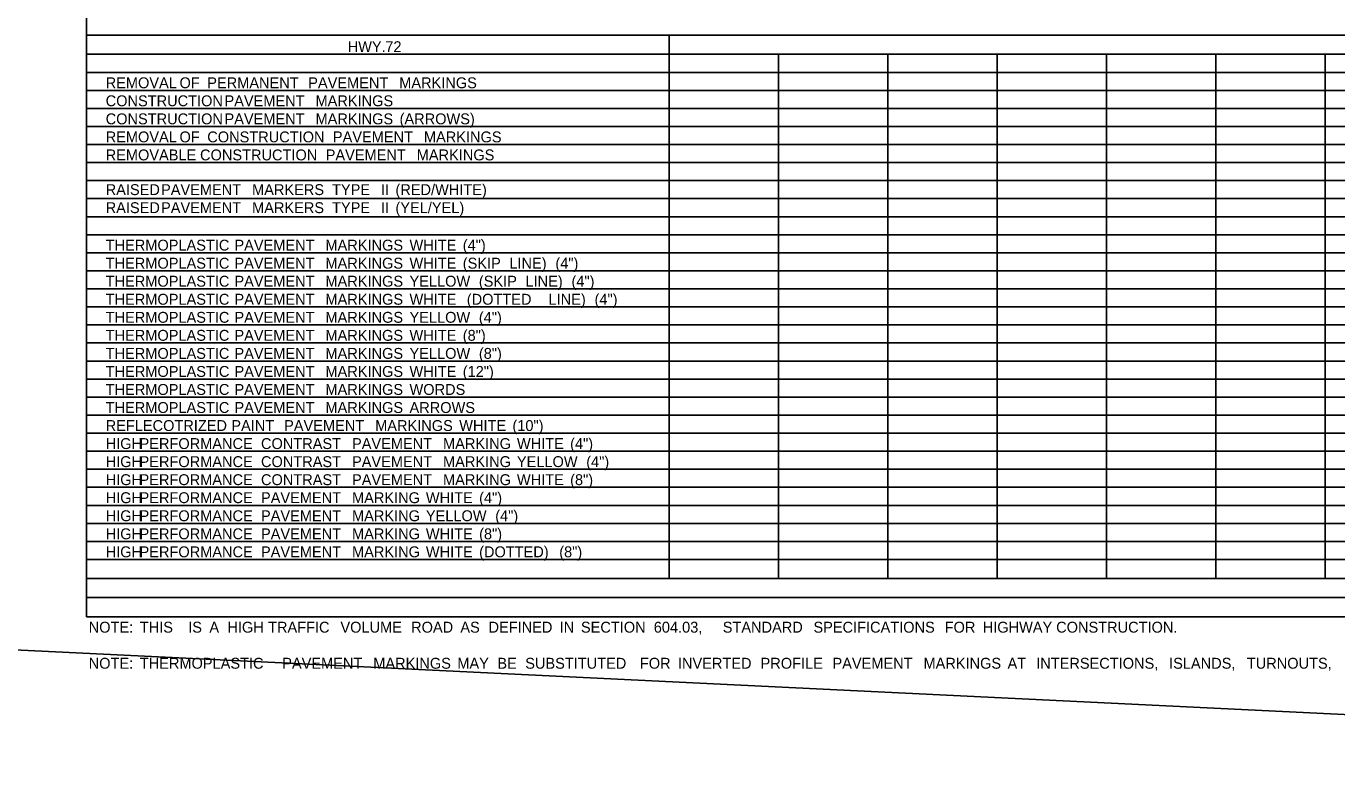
# Model space of a CAD drawing. Extents: x 1225909 to 1228704, y 151309 to 152305.
# Drawn here: x 1226559.5 to 1226949.3, y 151342 to 151561.1 of the extents above; entities that cross this region are included whole.
import ezdxf

# ---------------------------------------------------------------- set-up
doc = ezdxf.new("R2010")
doc.units = 0
doc.layers.add('R_Border', color=7, linetype='Continuous')
doc.layers.add('R_Dimension', color=7, linetype='Continuous')

msp = doc.modelspace()

# ---------------------------------------------------------------- linework, layer by layer
at = {"layer": 'R_Border'}
msp.add_lwpolyline([(1227672.06, 151397.84), (1227247.19, 151342), (1225968.58, 151404.15)], dxfattribs=at)
at = {"layer": 'R_Dimension'}
for p, q in [((1226577.42, 151385.44), (1226577.42, 151914.54)), ((1226577.42, 151558.44), (1228151.92, 151558.44)), ((1226750.73, 151396.81), (1226750.73, 151558.44)), ((1226577.42, 151552.76), (1228151.92, 151552.76)), ((1226783.25, 151396.81), (1226783.25, 151552.76)), ((1226815.77, 151396.81), (1226815.77, 151552.76)), ((1226848.28, 151396.81), (1226848.28, 151552.76)), ((1226880.8, 151396.81), (1226880.8, 151552.76)), ((1226913.31, 151396.81), (1226913.31, 151552.76)), ((1226945.83, 151396.81), (1226945.83, 151552.76)), ((1226577.42, 151547.39), (1228151.92, 151547.39)), ((1226577.42, 151542.02), (1228151.92, 151542.02)), ((1226577.42, 151536.66), (1228151.92, 151536.66)), ((1226577.42, 151531.29), (1228151.92, 151531.29)), ((1226577.42, 151525.92), (1228151.92, 151525.92)), ((1226577.42, 151520.56), (1228151.92, 151520.56)), ((1226577.42, 151515.19), (1228151.92, 151515.19)), ((1226577.42, 151509.82), (1228151.92, 151509.82)), ((1226577.42, 151504.46), (1228151.92, 151504.46)), ((1226577.42, 151499.09), (1228151.92, 151499.09)), ((1226577.42, 151493.72), (1228151.92, 151493.72)), ((1226577.42, 151488.36), (1228151.92, 151488.36)), ((1226577.42, 151482.99), (1228151.92, 151482.99)), ((1226577.42, 151477.62), (1228151.92, 151477.62)), ((1226577.42, 151472.26), (1228151.92, 151472.26)), ((1226577.42, 151466.89), (1228151.92, 151466.89)), ((1226577.42, 151461.52), (1228151.92, 151461.52)), ((1226577.42, 151456.16), (1228151.92, 151456.16)), ((1226577.42, 151450.79), (1228151.92, 151450.79)), ((1226577.42, 151445.42), (1228151.92, 151445.42)), ((1226577.42, 151440.06), (1228151.92, 151440.06)), ((1226577.42, 151434.69), (1228151.92, 151434.69)), ((1226577.42, 151429.32), (1228151.92, 151429.32)), ((1226577.42, 151423.96), (1228151.92, 151423.96)), ((1226577.42, 151418.59), (1228151.92, 151418.59)), ((1226577.42, 151413.22), (1228151.92, 151413.22)), ((1226577.42, 151407.86), (1228151.92, 151407.86)), ((1226577.42, 151402.49), (1228151.92, 151402.49)), ((1226577.42, 151396.81), (1228151.92, 151396.81)), ((1226577.42, 151391.13), (1228151.92, 151391.13)), ((1226577.42, 151385.44), (1228151.92, 151385.44))]:
    msp.add_line(p, q, dxfattribs=at)

# ---------------------------------------------------------------- texts
for s, height, p in [('HWY.', 3.238, (1226655.09, 151553.41)), (' 72', 3.238, (1226665.08, 151553.41)), ('REMOVAL', 3.238, (1226583.1, 151542.67)), (' OF', 3.238, (1226603.86, 151542.67)), (' PERMANENT', 3.238, (1226612.12, 151542.67)), (' PAVEMENT', 3.238, (1226642.15, 151542.67)), (' MARKINGS', 3.238, (1226669.22, 151542.67)), ('CONSTRUCTION', 3.2378, (1226583.1, 151537.31)), (' PAVEMENT', 3.238, (1226617.24, 151537.31)), (' MARKINGS', 3.238, (1226644.32, 151537.31)), ('CONSTRUCTION', 3.2378, (1226583.1, 151531.94)), (' PAVEMENT', 3.238, (1226617.24, 151531.94)), (' MARKINGS', 3.238, (1226644.32, 151531.94)), (' (ARROWS)', 3.238, (1226669.33, 151531.94)), ('REMOVAL', 3.238, (1226583.1, 151526.57)), (' OF', 3.238, (1226603.86, 151526.57)), (' CONSTRUCTION', 3.2378, (1226612.12, 151526.57)), (' PAVEMENT', 3.238, (1226649.49, 151526.57)), (' MARKINGS', 3.238, (1226676.57, 151526.57)), ('REMOVABLE', 3.238, (1226583.1, 151521.21)), (' CONSTRUCTION', 3.2378, (1226609.97, 151521.21)), (' PAVEMENT', 3.238, (1226647.35, 151521.21)), (' MARKINGS', 3.238, (1226674.43, 151521.21)), ('RAISED', 3.238, (1226583.1, 151510.89)), (' PAVEMENT', 3.238, (1226598.37, 151510.89)), (' MARKERS', 3.238, (1226625.45, 151510.89)), (' TYPE', 3.238, (1226649.24, 151510.89)), (' II', 3.238, (1226663.79, 151510.89)), (' (RED/WHITE)', 3.2378, (1226668.1, 151510.89)), ('RAISED', 3.238, (1226583.1, 151505.52)), (' PAVEMENT', 3.238, (1226598.37, 151505.52)), (' MARKERS', 3.238, (1226625.45, 151505.52)), (' TYPE', 3.238, (1226649.24, 151505.52)), (' II', 3.238, (1226663.79, 151505.52)), (' (YEL/YEL)', 3.238, (1226668.1, 151505.52)), ('THERMOPLASTIC', 3.2378, (1226583.1, 151494.37)), (' PAVEMENT', 3.238, (1226620.2, 151494.37)), (' MARKINGS', 3.238, (1226647.27, 151494.37)), (' WHITE', 3.238, (1226672.28, 151494.37)), (' (4")', 3.238, (1226688.12, 151494.37)), ('THERMOPLASTIC', 3.2378, (1226583.1, 151489)), (' PAVEMENT', 3.238, (1226620.2, 151489)), (' MARKINGS', 3.238, (1226647.27, 151489)), (' WHITE', 3.238, (1226672.28, 151489)), (' (SKIP', 3.238, (1226688.12, 151489)), (' LINE)', 3.238, (1226701.98, 151489)), (' (4")', 3.238, (1226715.68, 151489)), ('THERMOPLASTIC', 3.2378, (1226583.1, 151483.64)), (' PAVEMENT', 3.238, (1226620.2, 151483.64)), (' MARKINGS', 3.238, (1226647.27, 151483.64)), (' YELLOW', 3.238, (1226672.28, 151483.64)), (' (SKIP', 3.238, (1226692.91, 151483.64)), (' LINE)', 3.238, (1226706.78, 151483.64)), (' (4")', 3.238, (1226720.47, 151483.64)), ('THERMOPLASTIC', 3.2378, (1226583.1, 151478.27)), (' PAVEMENT', 3.238, (1226620.2, 151478.27)), (' MARKINGS', 3.238, (1226647.27, 151478.27)), (' WHITE', 3.238, (1226672.28, 151478.27)), ('  (DOTTED', 3.238, (1226688.12, 151478.27)), (' LINE)', 3.238, (1226713.64, 151478.27)), (' (4")', 3.238, (1226727.33, 151478.27)), ('THERMOPLASTIC', 3.2378, (1226583.1, 151472.9)), (' PAVEMENT', 3.238, (1226620.2, 151472.9)), (' MARKINGS', 3.238, (1226647.27, 151472.9)), (' YELLOW', 3.238, (1226672.28, 151472.9)), (' (4")', 3.238, (1226692.91, 151472.9)), ('THERMOPLASTIC', 3.2378, (1226583.1, 151467.54)), (' PAVEMENT', 3.238, (1226620.2, 151467.54)), (' MARKINGS', 3.238, (1226647.27, 151467.54)), (' WHITE', 3.238, (1226672.28, 151467.54)), (' (8")', 3.238, (1226688.12, 151467.54)), ('THERMOPLASTIC', 3.2378, (1226583.1, 151462.17)), (' PAVEMENT', 3.238, (1226620.2, 151462.17)), (' MARKINGS', 3.238, (1226647.27, 151462.17)), (' YELLOW', 3.238, (1226672.28, 151462.17)), (' (8")', 3.238, (1226692.91, 151462.17)), ('THERMOPLASTIC', 3.2378, (1226583.1, 151456.8)), (' PAVEMENT', 3.238, (1226620.2, 151456.8)), (' MARKINGS', 3.238, (1226647.27, 151456.8)), (' WHITE', 3.238, (1226672.28, 151456.8)), (' (12")', 3.238, (1226688.12, 151456.8)), ('THERMOPLASTIC', 3.2378, (1226583.1, 151451.44)), (' PAVEMENT', 3.238, (1226620.2, 151451.44)), (' MARKINGS', 3.238, (1226647.27, 151451.44)), (' WORDS', 3.238, (1226672.28, 151451.44)), ('THERMOPLASTIC', 3.2378, (1226583.1, 151446.07)), (' PAVEMENT', 3.238, (1226620.2, 151446.07)), (' MARKINGS', 3.238, (1226647.27, 151446.07)), (' ARROWS', 3.238, (1226672.28, 151446.07)), ('REFLECOTRIZED', 3.2378, (1226583.1, 151440.7)), (' PAINT', 3.238, (1226619.28, 151440.7)), (' PAVEMENT', 3.238, (1226634.98, 151440.7)), (' MARKINGS', 3.238, (1226662.06, 151440.7)), (' WHITE', 3.238, (1226687.07, 151440.7)), (' (10")', 3.238, (1226702.9, 151440.7)), ('HIGH', 3.238, (1226583.1, 151435.34)), (' PERFORMANCE', 3.2378, (1226591.97, 151435.34)), (' CONTRAST', 3.238, (1226628.1, 151435.34)), (' PAVEMENT', 3.238, (1226655.18, 151435.34)), (' MARKING', 3.238, (1226682.25, 151435.34)), (' WHITE', 3.238, (1226704.23, 151435.34)), (' (4")', 3.238, (1226720.06, 151435.34)), ('HIGH', 3.238, (1226583.1, 151429.97)), (' PERFORMANCE', 3.2378, (1226591.97, 151429.97)), (' CONTRAST', 3.238, (1226628.1, 151429.97)), (' PAVEMENT', 3.238, (1226655.18, 151429.97)), (' MARKING', 3.238, (1226682.25, 151429.97)), (' YELLOW', 3.238, (1226704.23, 151429.97)), (' (4")', 3.238, (1226724.85, 151429.97)), ('HIGH', 3.238, (1226583.1, 151424.6)), (' PERFORMANCE', 3.2378, (1226591.97, 151424.6)), (' CONTRAST', 3.238, (1226628.1, 151424.6)), (' PAVEMENT', 3.238, (1226655.18, 151424.6)), (' MARKING', 3.238, (1226682.25, 151424.6)), (' WHITE', 3.238, (1226704.23, 151424.6)), (' (8")', 3.238, (1226720.06, 151424.6)), ('HIGH', 3.238, (1226583.1, 151419.24)), (' PERFORMANCE', 3.2378, (1226591.97, 151419.24)), (' PAVEMENT', 3.238, (1226628.1, 151419.24)), (' MARKING', 3.238, (1226655.18, 151419.24)), (' WHITE', 3.238, (1226677.15, 151419.24)), (' (4")', 3.238, (1226692.99, 151419.24)), ('HIGH', 3.238, (1226583.1, 151413.87)), (' PERFORMANCE', 3.2378, (1226591.97, 151413.87)), (' PAVEMENT', 3.238, (1226628.1, 151413.87)), (' MARKING', 3.238, (1226655.18, 151413.87)), (' YELLOW', 3.238, (1226677.15, 151413.87)), (' (4")', 3.238, (1226697.78, 151413.87)), ('HIGH', 3.238, (1226583.1, 151408.5)), (' PERFORMANCE', 3.2378, (1226591.97, 151408.5)), (' PAVEMENT', 3.238, (1226628.1, 151408.5)), (' MARKING', 3.238, (1226655.18, 151408.5)), (' WHITE', 3.238, (1226677.15, 151408.5)), (' (8")', 3.238, (1226692.99, 151408.5)), ('HIGH', 3.238, (1226583.1, 151403.14)), (' PERFORMANCE', 3.2378, (1226591.97, 151403.14)), (' PAVEMENT', 3.238, (1226628.1, 151403.14)), (' MARKING', 3.238, (1226655.18, 151403.14)), (' WHITE', 3.238, (1226677.15, 151403.14)), (' (DOTTED)', 3.238, (1226692.99, 151403.14)), (' (8")', 3.238, (1226716.82, 151403.14)), ('NOTE:', 3.238, (1226578.05, 151380.72)), ('  THIS', 3.238, (1226590.85, 151380.72)), (' IS', 3.238, (1226606.45, 151380.72)), (' A', 3.238, (1226612.75, 151380.72)), (' HIGH', 3.238, (1226618.1, 151380.72)), (' TRAFFIC', 3.238, (1226630.21, 151380.72)), (' VOLUME', 3.238, (1226651.73, 151380.72)), (' ROAD', 3.238, (1226672.76, 151380.72)), (' AS', 3.238, (1226687.4, 151380.72)), (' DEFINED', 3.238, (1226695.79, 151380.72)), (' IN', 3.238, (1226716.95, 151380.72)), (' SECTION', 3.238, (1226723.27, 151380.72)), (' 604.03,', 3.238, (1226744.94, 151380.72)), (' STANDARD', 3.238, (1226765.46, 151380.72)), (' SPECIFICATIONS', 3.2378, (1226792.44, 151380.72)), (' FOR', 3.238, (1226831.47, 151380.72)), (' HIGHWAY', 3.238, (1226842.79, 151380.72)), (' CONSTRUCTION.', 3.2378, (1226864.64, 151380.72)), ('NOTE:', 3.238, (1226578.05, 151369.99)), ('  THERMOPLASTIC', 3.2378, (1226590.85, 151369.99)), (' PAVEMENT', 3.238, (1226634.42, 151369.99)), (' MARKINGS', 3.238, (1226661.5, 151369.99)), (' MAY', 3.238, (1226686.51, 151369.99)), (' BE', 3.238, (1226698.41, 151369.99)), (' SUBSTITUTED', 3.2378, (1226706.7, 151369.99)), (' FOR', 3.238, (1226740.81, 151369.99)), (' INVERTED', 3.238, (1226752.13, 151369.99)), (' PROFILE', 3.238, (1226776.71, 151369.99)), (' PAVEMENT', 3.238, (1226798.1, 151369.99)), (' MARKINGS', 3.238, (1226825.17, 151369.99)), (' AT', 3.238, (1226850.18, 151369.99)), (' INTERSECTIONS,', 3.2378, (1226858.7, 151369.99)), (' ISLANDS,', 3.238, (1226898.24, 151369.99)), (' TURNOUTS,', 3.238, (1226921.36, 151369.99))]:
    msp.add_text(s, height=height, dxfattribs=at).set_placement(p)

doc.saveas('drawing.dxf')
